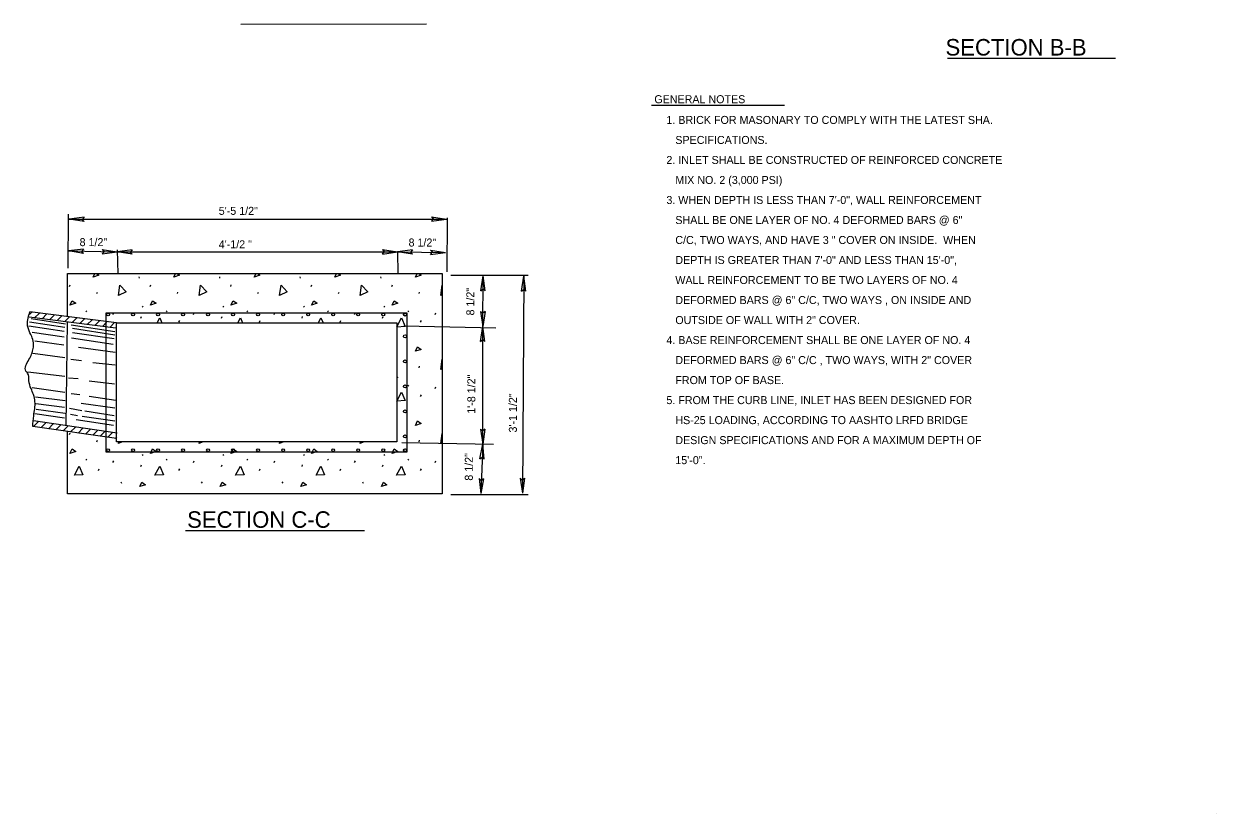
# Model space of a CAD drawing. Extents: x 0.9 to 8.1, y 0.4 to 10.5.
# Drawn here: x 0.96 to 8.11, y 0.37 to 5.1 of the extents above; entities that cross this region are included whole.
import ezdxf

# ---------------------------------------------------------------- set-up
doc = ezdxf.new("R2010")
doc.units = 0
for name, color, linetype in [('DETL-DIMS', 7, 'Continuous'), ('DETL-LINE', 7, 'Continuous'), ('DETL-NOTE', 7, 'Continuous'), ('DETL-TITL', 7, 'Continuous'), ('TTLB-TEXT', 7, 'Continuous')]:
    doc.layers.add(name, color=color, linetype=linetype)

msp = doc.modelspace()

# ---------------------------------------------------------------- linework, layer by layer
at = {"layer": 'DETL-DIMS'}
for p, q in [((1.2282, 3.6359), (1.2312, 3.9603)), ((1.3244, 3.9426), (1.2342, 3.9306)), ((1.3244, 3.9426), (1.3129, 3.9296)), ((3.408, 3.9447), (3.4978, 3.9305)), ((3.408, 3.9447), (3.419, 3.9315)), ((3.5013, 3.6151), (3.5043, 3.9394)), ((1.3241, 3.9164), (1.2342, 3.9306)), ((1.2342, 3.9305), (3.4978, 3.9305)), ((1.3241, 3.9164), (1.3129, 3.9296)), ((3.4076, 3.9184), (3.419, 3.9315)), ((3.4076, 3.9184), (3.4978, 3.9305)), ((1.3215, 3.7513), (1.2312, 3.7401)), ((1.2312, 3.7401), (1.5227, 3.7341)), ((1.3209, 3.7251), (1.2312, 3.7401)), ((1.3215, 3.7513), (1.31, 3.7385)), ((1.3209, 3.7251), (1.31, 3.7385)), ((1.4325, 3.7228), (1.444, 3.7357)), ((1.4325, 3.7228), (1.5227, 3.7342)), ((1.433, 3.7491), (1.5227, 3.7342)), ((1.433, 3.7491), (1.444, 3.7357)), ((1.6128, 3.7466), (1.5227, 3.7341)), ((1.6127, 3.7203), (1.5227, 3.7341)), ((1.5227, 3.7341), (3.2033, 3.7341)), ((1.6128, 3.7466), (1.6015, 3.7336)), ((1.6127, 3.7203), (1.6015, 3.7336)), ((3.1132, 3.7216), (3.1246, 3.7347)), ((3.1132, 3.7216), (3.2034, 3.7341)), ((3.1134, 3.7479), (3.2034, 3.7341)), ((3.1134, 3.7479), (3.1246, 3.7347)), ((3.2935, 3.7463), (3.2034, 3.7341)), ((3.2932, 3.7201), (3.2034, 3.7341)), ((3.2935, 3.7463), (3.2821, 3.7333)), ((3.2932, 3.7201), (3.2821, 3.7333)), ((3.4018, 3.719), (3.4131, 3.7319)), ((3.4018, 3.719), (3.4919, 3.7312)), ((3.402, 3.7452), (3.4919, 3.7312)), ((3.402, 3.7452), (3.4131, 3.7319)), ((3.5246, 3.5942), (3.9886, 3.5942)), ((3.7039, 3.5014), (3.7179, 3.5913)), ((3.7149, 3.2877), (3.7179, 3.5913)), ((3.7302, 3.5011), (3.7179, 3.5913)), ((3.9481, 3.4984), (3.9618, 3.5883)), ((3.9618, 3.5883), (3.9529, 2.2878)), ((3.9744, 3.4982), (3.9618, 3.5883)), ((3.7039, 3.5014), (3.7172, 3.5125)), ((3.7302, 3.5011), (3.7172, 3.5125)), ((3.9481, 3.4984), (3.9613, 3.5096)), ((3.9744, 3.4982), (3.9613, 3.5096)), ((3.7027, 3.3779), (3.715, 3.2877)), ((3.7027, 3.3779), (3.7157, 3.3665)), ((3.729, 3.3776), (3.715, 3.2877)), ((3.729, 3.3776), (3.7157, 3.3665)), ((3.7018, 3.1977), (3.715, 3.2877)), ((3.7149, 2.5824), (3.7149, 3.2877)), ((3.7281, 3.1977), (3.715, 3.2877)), ((3.7018, 3.1977), (3.715, 3.209)), ((3.7281, 3.1977), (3.715, 3.209)), ((3.7018, 2.6724), (3.715, 2.5824)), ((3.7018, 2.6724), (3.715, 2.6611)), ((3.7018, 2.6724), (3.715, 2.5824)), ((3.7018, 2.6724), (3.715, 2.6611)), ((3.7281, 2.6724), (3.715, 2.5824)), ((3.7281, 2.6724), (3.715, 2.6611)), ((3.7281, 2.6724), (3.715, 2.5824)), ((3.7281, 2.6724), (3.715, 2.6611)), ((3.6983, 2.493), (3.715, 2.5824)), ((3.7149, 2.5824), (3.703, 2.2848)), ((3.7245, 2.4919), (3.715, 2.5824)), ((3.6983, 2.493), (3.7118, 2.5037)), ((3.7245, 2.4919), (3.7118, 2.5037)), ((3.6936, 2.3753), (3.7031, 2.2848)), ((3.6936, 2.3753), (3.7062, 2.3635)), ((3.7198, 2.3742), (3.7031, 2.2848)), ((3.7198, 2.3742), (3.7062, 2.3635)), ((3.9404, 2.3779), (3.9529, 2.2878)), ((3.9404, 2.3779), (3.9535, 2.3665)), ((3.9404, 2.3779), (3.9529, 2.2878)), ((3.9404, 2.3779), (3.9535, 2.3665)), ((3.9667, 2.3777), (3.9529, 2.2878)), ((3.9667, 2.3777), (3.9529, 2.2878)), ((3.9667, 2.3777), (3.9535, 2.3665)), ((3.9667, 2.3777), (3.9535, 2.3665)), ((3.5246, 2.2788), (3.9886, 2.2788))]:
    msp.add_line(p, q, dxfattribs=at)
at = {"layer": 'DETL-LINE'}
for p, q in [((1.3789, 3.5832), (1.3893, 3.604)), ((1.653, 3.5857), (1.6542, 3.576)), ((1.862, 3.5832), (1.8723, 3.604)), ((2.1361, 3.5857), (2.1373, 3.576)), ((2.345, 3.5832), (2.3554, 3.604)), ((2.6192, 3.5857), (2.6204, 3.576)), ((2.8281, 3.5832), (2.8385, 3.604)), ((3.1023, 3.5857), (3.1035, 3.576)), ((3.3112, 3.5832), (3.3216, 3.604)), ((1.2376, 3.5277), (1.2412, 3.5373)), ((1.7207, 3.5277), (1.7243, 3.5373)), ((2.2037, 3.5277), (2.2074, 3.5373)), ((2.6868, 3.5277), (2.6905, 3.5373)), ((3.1699, 3.5277), (3.1735, 3.5373)), ((1.4006, 3.4842), (1.4042, 3.4939)), ((1.8837, 3.4842), (1.8873, 3.4939)), ((2.3668, 3.4842), (2.3704, 3.4939)), ((2.8499, 3.4842), (2.8535, 3.4939)), ((3.333, 3.4842), (3.3366, 3.4939)), ((3.4721, 3.4774), (3.4634, 3.4733)), ((0.9968, 3.3598), (1.0108, 3.3738)), ((1.5187, 3.309), (0.9988, 3.3753)), ((1.0275, 3.3396), (1.056, 3.368)), ((1.0727, 3.3338), (1.1011, 3.3622)), ((1.3342, 3.3803), (1.339, 3.3743)), ((1.4972, 3.3598), (1.5021, 3.3695)), ((1.6736, 3.4081), (1.6772, 3.4021)), ((1.8173, 3.3803), (1.8221, 3.3743)), ((1.9803, 3.3598), (1.9851, 3.3695)), ((2.1566, 3.4081), (2.1603, 3.4021)), ((2.3004, 3.3803), (2.3052, 3.3743)), ((2.4634, 3.3598), (2.4682, 3.3695)), ((2.6397, 3.4081), (2.6434, 3.4021)), ((2.7835, 3.3803), (2.7883, 3.3743)), ((2.9465, 3.3598), (2.9513, 3.3695)), ((3.1228, 3.4081), (3.1264, 3.4021)), ((3.2665, 3.3803), (3.2714, 3.3743)), ((3.4296, 3.3598), (3.4344, 3.3695)), ((0.9926, 3.2911), (1.2044, 3.2589)), ((1.5147, 3.2774), (0.9948, 3.3437)), ((0.9976, 3.3146), (1.2081, 3.2836)), ((1.0062, 3.3344), (1.213, 3.3022)), ((1.1178, 3.328), (1.1463, 3.3565)), ((1.163, 3.3223), (1.1914, 3.3507)), ((1.2081, 3.3165), (1.2366, 3.345)), ((1.2177, 2.6923), (1.2256, 3.3143)), ((1.2477, 3.2973), (1.509, 3.2576)), ((1.2533, 3.3107), (1.2817, 3.3392)), ((1.2984, 3.305), (1.3269, 3.3334)), ((1.3436, 3.2992), (1.372, 3.3277)), ((1.3887, 3.2935), (1.4172, 3.3219)), ((1.415, 3.3222), (1.4151, 3.3224)), ((1.4339, 3.2877), (1.4623, 3.3162)), ((1.479, 3.2819), (1.5075, 3.3104)), ((1.6651, 3.3369), (1.6687, 3.3465)), ((1.8934, 3.3127), (1.8982, 3.3224)), ((2.1482, 3.3369), (2.1518, 3.3465)), ((2.3765, 3.3127), (2.3813, 3.3224)), ((2.6313, 3.3369), (2.6349, 3.3465)), ((2.8595, 3.3127), (2.8644, 3.3224)), ((3.1144, 3.3369), (3.118, 3.3465)), ((3.3426, 3.3127), (3.3475, 3.3224)), ((1.0124, 3.2539), (1.2044, 3.2242)), ((1.2489, 3.2192), (1.4991, 3.1808)), ((1.2551, 3.2762), (1.5077, 3.2366)), ((1.2551, 3.2502), (1.504, 3.2143)), ((1.0298, 3.2019), (1.2031, 3.1771)), ((1.291, 3.1635), (1.5102, 3.1325)), ((1.0174, 3.1263), (1.2081, 3.1003)), ((1.244, 3.0916), (1.3096, 3.0829)), ((0.9877, 3.0148), (1.2081, 2.9888)), ((1.5102, 3.0557), (1.3777, 3.0693)), ((3.333, 3.0398), (3.3366, 3.0494)), ((3.4721, 3.033), (3.4634, 3.0289)), ((1.2316, 2.9789), (1.2886, 2.9752)), ((1.3542, 2.9615), (1.5065, 2.9442)), ((3.2665, 2.9359), (3.2714, 2.9299)), ((1.0137, 2.9207), (1.2081, 2.8934)), ((1.0335, 2.8661), (1.2118, 2.8426)), ((1.2465, 2.886), (1.2985, 2.8798)), ((1.3542, 2.8686), (1.5139, 2.8451)), ((3.3426, 2.8683), (3.3475, 2.8779)), ((3.4296, 2.9154), (3.4344, 2.925)), ((1.0347, 2.8253), (1.2068, 2.8042)), ((1.036, 2.7918), (1.2106, 2.767)), ((1.2366, 2.7968), (1.3099, 2.7829)), ((1.3059, 2.8277), (1.509, 2.7993)), ((1.5235, 2.6479), (1.0209, 2.7208)), ((1.0285, 2.7646), (1.2068, 2.7398)), ((1.2427, 2.7621), (1.2839, 2.7538)), ((1.2762, 2.7286), (1.5003, 2.6964)), ((1.3121, 2.7485), (1.5077, 2.7224)), ((1.3282, 2.7807), (1.5052, 2.7534)), ((1.5187, 2.6149), (1.0162, 2.6878)), ((1.0214, 2.687), (1.0509, 2.7165)), ((1.0659, 2.6805), (1.0954, 2.71)), ((1.1103, 2.6741), (1.1398, 2.7036)), ((1.1548, 2.6676), (1.1843, 2.6971)), ((1.1993, 2.6612), (1.2288, 2.6907)), ((1.2376, 2.6388), (1.2412, 2.6485)), ((1.2437, 2.6547), (1.2732, 2.6842)), ((1.2882, 2.6483), (1.3177, 2.6778)), ((1.3327, 2.6419), (1.3621, 2.6713)), ((1.3771, 2.6354), (1.4066, 2.6649)), ((1.4216, 2.629), (1.4511, 2.6585)), ((1.4661, 2.6225), (1.4955, 2.652)), ((1.4006, 2.5953), (1.4042, 2.605)), ((1.5105, 2.6161), (1.5203, 2.6259)), ((1.531, 2.5845), (1.5325, 2.595)), ((1.5534, 2.595), (1.531, 2.5845)), ((2.0141, 2.5845), (2.0156, 2.595)), ((2.0365, 2.595), (2.0141, 2.5845)), ((2.4972, 2.5845), (2.4987, 2.595)), ((2.5195, 2.595), (2.4972, 2.5845)), ((2.9803, 2.5845), (2.9818, 2.595)), ((3.0026, 2.595), (2.9803, 2.5845)), ((3.333, 2.5953), (3.3366, 2.605)), ((3.4721, 2.5886), (3.4634, 2.5845)), ((1.6736, 2.5192), (1.6772, 2.5132)), ((2.1566, 2.5192), (2.1603, 2.5132)), ((2.6397, 2.5192), (2.6434, 2.5132)), ((3.1228, 2.5192), (3.1264, 2.5132)), ((1.3342, 2.4915), (1.339, 2.4854)), ((1.4103, 2.4238), (1.4151, 2.4335)), ((1.4972, 2.4709), (1.5021, 2.4806)), ((1.6651, 2.448), (1.6687, 2.4576)), ((1.8173, 2.4915), (1.8221, 2.4854)), ((1.8934, 2.4238), (1.8982, 2.4335)), ((1.9803, 2.4709), (1.9851, 2.4806)), ((2.1482, 2.448), (2.1518, 2.4576)), ((2.3004, 2.4915), (2.3052, 2.4854)), ((2.3765, 2.4238), (2.3813, 2.4335)), ((2.4634, 2.4709), (2.4682, 2.4806)), ((2.6313, 2.448), (2.6349, 2.4576)), ((2.7835, 2.4915), (2.7883, 2.4854)), ((2.8595, 2.4238), (2.8644, 2.4335)), ((2.9465, 2.4709), (2.9513, 2.4806)), ((3.1144, 2.448), (3.118, 2.4576)), ((3.2665, 2.4915), (3.2714, 2.4854)), ((3.3426, 2.4238), (3.3475, 2.4335)), ((3.4296, 2.4709), (3.4344, 2.4806)), ((1.5443, 2.355), (1.5492, 2.3477)), ((2.0274, 2.355), (2.0323, 2.3477)), ((2.5105, 2.355), (2.5153, 2.3477)), ((2.9936, 2.355), (2.9984, 2.3477))]:
    msp.add_line(p, q, dxfattribs=at)
for points in [[(1.2243, 3.3465), (1.2243, 3.604), (3.4721, 3.604), (3.4721, 2.2843), (1.2243, 2.2843), (1.2243, 2.6576)], [(1.3997, 3.604), (1.4127, 3.5941), (1.3789, 3.5832)], [(1.8828, 3.604), (1.8958, 3.5941), (1.862, 3.5832)], [(2.3659, 3.604), (2.3789, 3.5941), (2.345, 3.5832)], [(2.849, 3.604), (2.862, 3.5941), (2.8281, 3.5832)], [(3.3321, 3.604), (3.345, 3.5941), (3.3112, 3.5832)], [(1.531, 3.4733), (1.5395, 3.5349), (1.5769, 3.4951), (1.531, 3.4733)], [(2.0141, 3.4733), (2.0226, 3.5349), (2.06, 3.4951), (2.0141, 3.4733)], [(2.4972, 3.4733), (2.5057, 3.5349), (2.5431, 3.4951), (2.4972, 3.4733)], [(2.9803, 3.4733), (2.9888, 3.5349), (3.0262, 3.4951), (2.9803, 3.4733)], [(3.4634, 3.4733), (3.4719, 3.5349), (3.4721, 3.5347)], [(1.2388, 3.4154), (1.2521, 3.4419), (1.2738, 3.4262), (1.2388, 3.4154)], [(1.7219, 3.4154), (1.7352, 3.4419), (1.7569, 3.4262), (1.7219, 3.4154)], [(2.205, 3.4154), (2.2182, 3.4419), (2.24, 3.4262), (2.205, 3.4154)], [(2.688, 3.4154), (2.7013, 3.4419), (2.7231, 3.4262), (2.688, 3.4154)], [(3.1711, 3.4154), (3.1844, 3.4419), (3.2062, 3.4262), (3.1711, 3.4154)], [(1.2952, 3.3375), (1.2955, 3.3381), (1.2958, 3.3374)], [(1.7631, 3.309), (1.7786, 3.3381), (1.7911, 3.309)], [(2.2462, 3.309), (2.2617, 3.3381), (2.2742, 3.309)], [(2.7293, 3.309), (2.7448, 3.3381), (2.7573, 3.309)], [(3.1992, 3.2842), (3.2279, 3.3381), (3.2496, 3.2874), (3.1992, 3.2837)], [(3.3112, 3.1388), (3.3245, 3.1654), (3.345, 3.1497), (3.3112, 3.1388)], [(3.4634, 3.0289), (3.4719, 3.0905), (3.4721, 3.0903)], [(3.1992, 2.9868), (3.2062, 2.9818), (3.1992, 2.9796)], [(3.1992, 2.8398), (3.2279, 2.8936), (3.2496, 2.8429), (3.1992, 2.8393)], [(3.3112, 2.6944), (3.3245, 2.7209), (3.345, 2.7052), (3.3112, 2.6944)], [(3.4634, 2.5845), (3.4719, 2.6461), (3.4721, 2.6458)], [(1.2388, 2.5265), (1.2521, 2.5531), (1.2738, 2.5374), (1.2388, 2.5265)], [(1.7219, 2.5265), (1.7352, 2.5531), (1.7569, 2.5374), (1.7219, 2.5265)], [(2.205, 2.5265), (2.2182, 2.5531), (2.24, 2.5374), (2.205, 2.5265)], [(2.688, 2.5265), (2.7013, 2.5531), (2.7231, 2.5374), (2.688, 2.5265)], [(3.1711, 2.5265), (3.1844, 2.5531), (3.2062, 2.5374), (3.1711, 2.5265)], [(1.2666, 2.3948), (1.2955, 2.4492), (1.3173, 2.3985), (1.2666, 2.3948)], [(1.7496, 2.3948), (1.7786, 2.4492), (1.8004, 2.3985), (1.7496, 2.3948)], [(2.2327, 2.3948), (2.2617, 2.4492), (2.2835, 2.3985), (2.2327, 2.3948)], [(2.7158, 2.3948), (2.7448, 2.4492), (2.7665, 2.3985), (2.7158, 2.3948)], [(3.1989, 2.3948), (3.2279, 2.4492), (3.2496, 2.3985), (3.1989, 2.3948)], [(1.6579, 2.3272), (1.6699, 2.3538), (1.6917, 2.3381), (1.6579, 2.3272)], [(2.1409, 2.3272), (2.153, 2.3538), (2.1748, 2.3381), (2.1409, 2.3272)], [(2.624, 2.3272), (2.6361, 2.3538), (2.6578, 2.3381), (2.624, 2.3272)], [(3.1071, 2.3272), (3.1192, 2.3538), (3.1409, 2.3381), (3.1071, 2.3272)]]:
    msp.add_lwpolyline(points, dxfattribs=at)
for points in [[(1.4577, 3.37), (3.2602, 3.37), (3.2602, 2.534), (1.4577, 2.534)], [(1.5187, 3.309), (3.1992, 3.309), (3.1992, 2.595), (1.5187, 2.595)]]:
    msp.add_lwpolyline(points, close=True, dxfattribs=at)
for centre in [(1.4682, 3.359), (1.6182, 3.359), (1.7682, 3.359), (1.9182, 3.359), (2.0682, 3.359), (2.2182, 3.359), (2.3682, 3.359), (2.5182, 3.359), (2.6682, 3.359), (2.8182, 3.359), (2.9682, 3.359), (3.1182, 3.359), (3.2492, 3.3586), (3.25, 3.359), (3.2492, 3.2279), (3.2492, 3.0779), (3.2492, 2.9279), (3.2492, 2.7779), (3.2492, 2.6279), (1.4682, 2.545), (1.6182, 2.545), (1.7682, 2.545), (1.9182, 2.545), (2.0682, 2.545), (2.2182, 2.545), (2.3682, 2.545), (2.5182, 2.545), (2.6682, 2.545), (2.8182, 2.545), (2.9682, 2.545), (3.1182, 2.545), (3.2492, 2.5454), (3.25, 2.545)]:
    msp.add_circle(centre, 0.00888, dxfattribs=at)
msp.add_spline([(1.0162, 2.6878), (1.0223, 2.7522), (1.0298, 2.8364), (1.0211, 2.8785), (1.0062, 2.9145), (0.9939, 2.9628), (0.9852, 3.0074), (0.9753, 3.0198), (0.9939, 3.0891), (1.0186, 3.1548), (1.0211, 3.1895), (1.01, 3.2279), (0.9902, 3.2725), (0.9852, 3.2985), (0.9988, 3.3753)], degree=3, dxfattribs=at)
at = {"layer": 'DETL-NOTE'}
for p, q in [((4.727, 4.6136), (5.5259, 4.6136)), ((1.5227, 3.746), (1.5257, 3.6032)), ((3.2033, 3.7341), (3.4918, 3.7311)), ((3.2033, 3.7341), (3.2063, 3.6032)), ((3.243, 3.2901), (3.7934, 3.2799)), ((3.2301, 2.5913), (3.7806, 2.5812))]:
    msp.add_line(p, q, dxfattribs=at)
at = {"layer": 'DETL-TITL'}
for p, q in [((2.2639, 5.0997), (3.3775, 5.1019)), ((6.5032, 4.896), (7.5106, 4.896)), ((1.9329, 2.0641), (3.0057, 2.0641))]:
    msp.add_line(p, q, dxfattribs=at)
at = {"layer": 'TTLB-TEXT'}
msp.add_line((8.114, 0.369), (8.114, 0.369), dxfattribs=at)

# ---------------------------------------------------------------- texts
at = {"layer": 'DETL-NOTE'}
for s, p in [('GENERAL NOTES', (4.7443, 4.6259)), ('1. BRICK FOR MASONARY TO COMPLY WITH THE LATEST SHA. ', (4.8168, 4.5017)), ('   SPECIFICATIONS.', (4.8168, 4.3817)), ('2. INLET SHALL BE CONSTRUCTED OF REINFORCED CONCRETE ', (4.8168, 4.2617)), ('   MIX NO. 2 (3,000 PSI)', (4.8168, 4.1417)), ('3. WHEN DEPTH IS LESS THAN 7\'-0", WALL REINFORCEMENT ', (4.8168, 4.0217)), ('   SHALL BE ONE LAYER OF NO. 4 DEFORMED BARS @ 6" ', (4.8168, 3.9017)), ('4\'-1/2 "', (2.1318, 3.7559)), ('   C/C, TWO WAYS, AND HAVE 3 " COVER ON INSIDE.  WHEN', (4.8168, 3.7817)), ('   DEPTH IS GREATER THAN 7\'-0" AND LESS THAN 15\'-0", ', (4.8168, 3.6617)), ('   WALL REINFORCEMENT TO BE TWO LAYERS OF NO. 4 ', (4.8168, 3.5417)), ('   DEFORMED BARS @ 6" C/C, TWO WAYS , ON INSIDE AND ', (4.8168, 3.4217)), ('   OUTSIDE OF WALL WITH 2" COVER.', (4.8168, 3.3017)), ('4. BASE REINFORCEMENT SHALL BE ONE LAYER OF NO. 4 ', (4.8168, 3.1817)), ('   DEFORMED BARS @ 6" C/C , TWO WAYS, WITH 2" COVER ', (4.8168, 3.0617)), ('   FROM TOP OF BASE.', (4.8168, 2.9417)), ('5. FROM THE CURB LINE, INLET HAS BEEN DESIGNED FOR ', (4.8168, 2.8217)), ('   HS-25 LOADING, ACCORDING TO AASHTO LRFD BRIDGE ', (4.8168, 2.7017)), ('   DESIGN SPECIFICATIONS AND FOR A MAXIMUM DEPTH OF ', (4.8168, 2.5817)), ('   15\'-0".', (4.8168, 2.4617))]:
    msp.add_text(s, height=0.048, dxfattribs=at).set_placement(p)
for s, rotation, p in [('5\'-5 1/2"', 360, (2.1318, 3.9565)), ('8 1/2"', 360, (1.2973, 3.7689)), ('8 1/2"', 360, (3.2704, 3.7667)), ('8 1/2"', 90, (3.665, 3.3531)), ('1\'-8 1/2"', 90, (3.671, 2.7637)), ('3\'-1 1/2"', 90, (3.9201, 2.6513)), ('8 1/2"', 90, (3.6558, 2.3626))]:
    msp.add_text(s, height=0.048, rotation=rotation, dxfattribs=at).set_placement(p)
at = {"layer": 'DETL-TITL'}
for s, p in [('SECTION B-B', (6.4908, 4.9119)), ('SECTION C-C', (1.9424, 2.08))]:
    msp.add_text(s, height=0.099, dxfattribs=at).set_placement(p)

doc.saveas('drawing.dxf')
